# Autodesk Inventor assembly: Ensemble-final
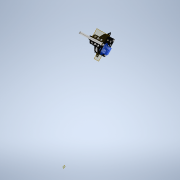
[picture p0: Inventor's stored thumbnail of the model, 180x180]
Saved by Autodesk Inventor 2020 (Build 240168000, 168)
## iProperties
Created: 2021-10
Part Number: Ensemble-final
Document SubType Name: Assembly
Designer: bruno
Mass: 18.8256 g
Surface Area: 254.134 cm^2
Volume: 12.2422 cm^3
Density: 1.53777 g/cm^3
Author: bruno
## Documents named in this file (5)
- C:\Users\bruno\OneDrive\Bureau\Robot-Inventor\Robot-equilibrage\Ensemble-final.iam
- C:\Users\bruno\OneDrive\Bureau\Robot-Inventor\Robot-equilibrage\Ensemble-corps.iam
- C:\Users\bruno\OneDrive\Bureau\Robot-Inventor\Robot-equilibrage\Ensemble-pince.iam
- C:\Users\bruno\OneDrive\Bureau\Robot-Inventor\Robot-equilibrage\Ensemble-pince-2.iam
- C:\Users\bruno\OneDrive\Bureau\Robot-Inventor\Robot-equilibrage\Reglette-1.ipt
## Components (4 placed, 4 different names)
1. Ensemble-corps:1 [sub-assembly] — Placage:1, Logement:1, Angle:2
2. Ensemble-pince:1 [sub-assembly] — Placage:1, Affleurement:1, Rotation:1, Angle:1, Angle:2
3. Ensemble-pince-2:1 [sub-assembly] — Logement:1, Affleurement:1, Rotation:1, Affleurement:2, Affleurement:3, Angle:1
4. Reglette-1:1 — Affleurement:2, Affleurement:3
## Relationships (8: Flush 3, Angle 2, Mate 1, Insert 1, RelateRotation 1)
- Placage:1 [Mate]: Ensemble-corps:1 ↔ Ensemble-pince:1
- Logement:1 [Insert]: Ensemble-corps:1 ↔ Ensemble-pince-2:1
- Affleurement:1 [Flush]: Ensemble-pince:1 ↔ Ensemble-pince-2:1
- Rotation:1 [RelateRotation]: Ensemble-pince:1 ↔ Ensemble-pince-2:1
- Affleurement:2 [Flush]: Ensemble-pince-2:1 ↔ Reglette-1:1
- Affleurement:3 [Flush]: Ensemble-pince-2:1 ↔ Reglette-1:1
- Angle:1: Ensemble-pince:1 ↔ Ensemble-pince-2:1
- Angle:2: Ensemble-corps:1 ↔ Ensemble-pince:1
